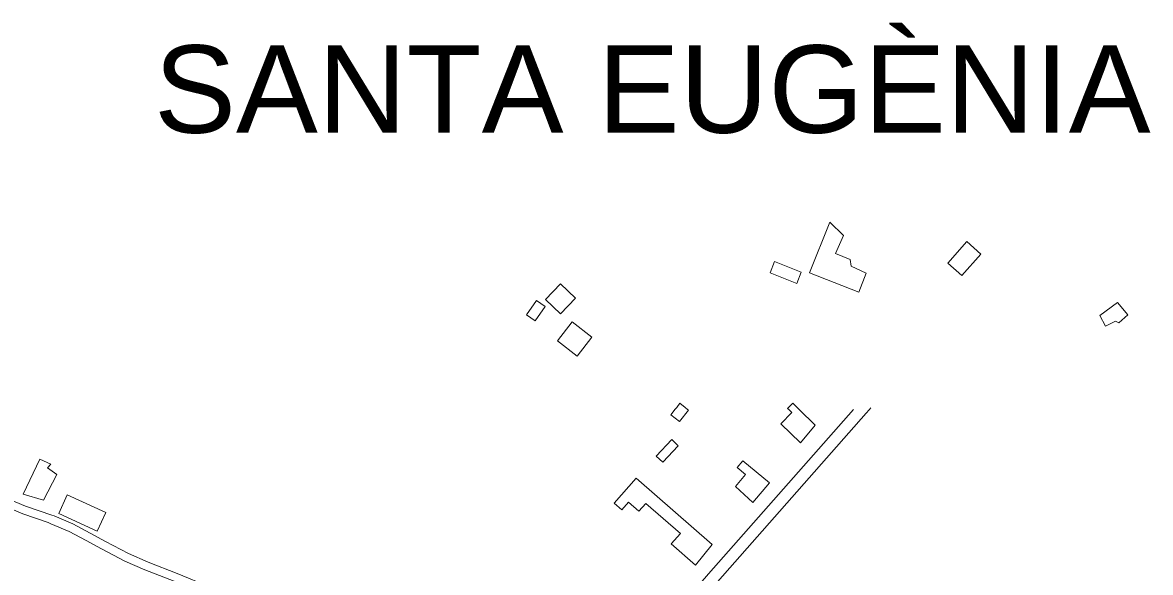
# Model space of a CAD drawing. Extents: x 476989 to 498418, y 4381813 to 4416555.
# Drawn here: x 486040 to 486556, y 4386368 to 4386620 of the extents above; entities that cross this region are included whole.
import ezdxf
from ezdxf.enums import TextEntityAlignment as Align

# ---------------------------------------------------------------- set-up
doc = ezdxf.new("R2010")
doc.units = 0
doc.header["$LTSCALE"] = 20
doc.layers.add('36', color=7, linetype='Continuous', lineweight=13)
doc.layers.add('47', color=7, linetype='Continuous', lineweight=13)
doc.layers.add('7', color=7, linetype='Continuous')

msp = doc.modelspace()

# ---------------------------------------------------------------- linework, layer by layer
at = {"layer": '36'}
msp.add_line((486426.98, 4386442.73), (486427.72, 4386443.62), dxfattribs=at)
for points in [[(486304.43, 4386310.75), (486353.58, 4386367.64), (486419.82, 4386442.75)], [(486308, 4386306.63), (486357.67, 4386364.07), (486425.71, 4386441.21), (486426.98, 4386442.73)], [(485974.99, 4386434.48), (485986.32, 4386427.31), (485994.65, 4386422.54), (485998.97, 4386420.3), (486002.25, 4386418.45), (486005.36, 4386415.71), (486009.59, 4386412.64), (486015.46, 4386408.13), (486019.91, 4386404.47), (486029.22, 4386399.61), (486040.03, 4386395.1), (486051.72, 4386391.11)], [(486053.43, 4386394.57), (486041.36, 4386398.68), (486030.81, 4386403.08), (486022.01, 4386407.71), (486017.89, 4386411.18), (486016, 4386412.63)], [(486166.79, 4386339.38), (486148.76, 4386348.75), (486138.31, 4386354.74), (486125.51, 4386361.79), (486110.65, 4386367.88), (486097.4, 4386373), (486088.44, 4386376.94), (486077.92, 4386382.5), (486070.93, 4386386.27), (486062.96, 4386390.53), (486054.41, 4386394.18), (486053.43, 4386394.57)], [(486165.01, 4386335.95), (486146.91, 4386345.36), (486136.42, 4386351.37), (486123.84, 4386358.3), (486109.22, 4386364.29), (486095.93, 4386369.43), (486086.76, 4386373.46), (486076.11, 4386379.09), (486069.11, 4386382.87), (486061.29, 4386387.04), (486052.94, 4386390.61), (486051.72, 4386391.11)]]:
    msp.add_lwpolyline(points, dxfattribs=at)
at = {"layer": '47'}
for p, q in [((486340.53, 4386445.65), (486339.06, 4386443.79)), ((486342.88, 4386443.78), (486340.53, 4386445.65)), ((486339.06, 4386443.79), (486338.35, 4386442.9)), ((486344, 4386442.89), (486342.88, 4386443.78)), ((486394.13, 4386443.68), (486395.05, 4386442.79))]:
    msp.add_line(p, q, dxfattribs=at)
for points in [[(486409.02, 4386528.55), (486399.69, 4386505.35), (486422.22, 4386496.55), (486425.65, 4386505.21), (486418.79, 4386508.38), (486418.31, 4386511.39), (486411.67, 4386514.18), (486415.31, 4386522.39)], [(486478.07, 4386513.91), (486469.4, 4386504.07), (486462.93, 4386509.77), (486471.6, 4386519.61)], [(486393.91, 4386500.41), (486381.69, 4386505.37), (486383.78, 4386510.53), (486396, 4386505.57)], [(486279, 4386493.2), (486285.91, 4386486.53), (486292.82, 4386493.68), (486285.91, 4386500.35)], [(486274.94, 4386492.66), (486270.38, 4386486.19), (486274.29, 4386483.44), (486278.85, 4386489.91)], [(486532.52, 4386485.82), (486540.48, 4386491.78), (486545.21, 4386486.16), (486541.1, 4386482.39), (486539.61, 4386483.16), (486535, 4386480.9)], [(486291.24, 4386482.97), (486300.3, 4386475.94), (486293.56, 4386467.25), (486284.5, 4386474.28)], [(486332.64, 4386418.75), (486339.77, 4386426.25), (486336.84, 4386429.04), (486329.71, 4386421.54)], [(486040.31, 4386404.1), (486047.89, 4386420.05), (486052.89, 4386417.8), (486051.44, 4386416.1), (486055.67, 4386413.11), (486049.58, 4386401.34)], [(486373.87, 4386400.22), (486381.43, 4386409.34), (486369.27, 4386419.41), (486366.68, 4386416.28), (486370.52, 4386413.09), (486365.92, 4386407.55)], [(486355.21, 4386381.13), (486320.45, 4386411.42), (486310.48, 4386399.99), (486313.89, 4386397.01), (486316.94, 4386400.51), (486321.78, 4386396.28), (486324.93, 4386399.9), (486340.75, 4386386.13), (486336.55, 4386381.32), (486347.55, 4386371.69)], [(486056.54, 4386395.24), (486074.12, 4386387.23), (486078.01, 4386395.76), (486060.43, 4386403.77)]]:
    msp.add_lwpolyline(points, close=True, dxfattribs=at)
for points in [[(486390.13, 4386443.69), (486392.06, 4386445.69), (486394.13, 4386443.68)], [(486338.35, 4386442.9), (486336.4, 4386440.44), (486340.33, 4386437.32), (486344.46, 4386442.53), (486344, 4386442.89)], [(486395.57, 4386427.52), (486386.62, 4386436.28), (486391.64, 4386441.42), (486390.22, 4386442.8)], [(486390.22, 4386442.8), (486389.73, 4386443.28), (486390.13, 4386443.69)], [(486395.05, 4386442.79), (486402.37, 4386435.71), (486395.57, 4386427.52)]]:
    msp.add_lwpolyline(points, dxfattribs=at)

# ---------------------------------------------------------------- texts
at = {"layer": '7', "width": 1.05}
msp.add_text('SANTA EUGÈNIA', height=40, dxfattribs=at).set_placement((486327.89, 4386569.36), align=Align.CENTER)

doc.saveas('drawing.dxf')
